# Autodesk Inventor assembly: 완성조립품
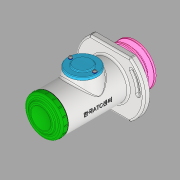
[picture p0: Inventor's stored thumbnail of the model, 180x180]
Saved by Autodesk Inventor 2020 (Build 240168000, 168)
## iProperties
Created: 2022-05
Part Number: 완성조립품
Document SubType Name: Assembly
Designer: User
Author: User
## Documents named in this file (22)
- C:\Users\User\Desktop\720506V1034\완성조립품.iam
- C:\Users\User\Desktop\720506V1034\본체.ipt
- C:\Users\User\Desktop\720506V1034\Ű 4 x 4.ipt
- C:\Users\User\Desktop\720506V1034\V-벨트풀리.ipt
- C:\Users\User\Desktop\720506V1034\개스킷.ipt
- C:\Users\User\Desktop\720506V1034\너트 M10.ipt
- C:\Users\User\Desktop\720506V1034\멈춤나사 M3.ipt
- C:\Users\User\Desktop\720506V1034\멈춤링 15 x 1.ipt
- C:\Users\User\Desktop\720506V1034\멈춤링 35 x 1.6.ipt
- C:\Users\User\Desktop\720506V1034\베어링 6202.ipt
- C:\Users\User\Desktop\720506V1034\볼트 M4 x 10.ipt
- C:\Users\User\Desktop\720506V1034\부시1.ipt
- C:\Users\User\Desktop\720506V1034\부시2.ipt
- C:\Users\User\Desktop\720506V1034\사이드 커버.ipt
- 사이드 커버.ipt
- C:\Users\User\Desktop\720506V1034\십자볼트 M3 x 10.ipt
- C:\Users\User\Desktop\720506V1034\오일 실 15 x 30 x 7.ipt
- C:\Users\User\Desktop\720506V1034\와셔 3 x 6.ipt
- C:\Users\User\Desktop\720506V1034\와셔 4 x 16.ipt
- C:\Users\User\Desktop\720506V1034\와셔 10 x 21.ipt
- C:\Users\User\Desktop\720506V1034\축.ipt
- C:\Users\User\Desktop\720506V1034\탑 커버.ipt
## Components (4 placed, 4 different names)
1. Ű 4 x 4:1 — 각도:2, 각도:10, 각도:18
2. V-벨트풀리:1 — 각도:8, 각도:9, 각도:11, 각도:12, 각도:13, 각도:14, 각도:15, 각도:16, 각도:17
3. 개스킷:1 — 각도:7
4. ISO 4017 M4 x 10:1 — 각도:2
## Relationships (13: Angle 13)
- 각도:2 [Angle]: Ű 4 x 4:1 ↔ ISO 4017 M4 x 10:1
- 각도:7 [Angle]: 개스킷:1
- 각도:8 [Angle]: V-벨트풀리:1
- 각도:9 [Angle]: V-벨트풀리:1
- 각도:10 [Angle]: Ű 4 x 4:1
- 각도:11 [Angle]: V-벨트풀리:1
- 각도:12 [Angle]: V-벨트풀리:1
- 각도:13 [Angle]: V-벨트풀리:1
- 각도:14 [Angle]: V-벨트풀리:1
- 각도:15 [Angle]: V-벨트풀리:1
- 각도:16 [Angle]: V-벨트풀리:1
- 각도:17 [Angle]: V-벨트풀리:1
- 각도:18 [Angle]: Ű 4 x 4:1
